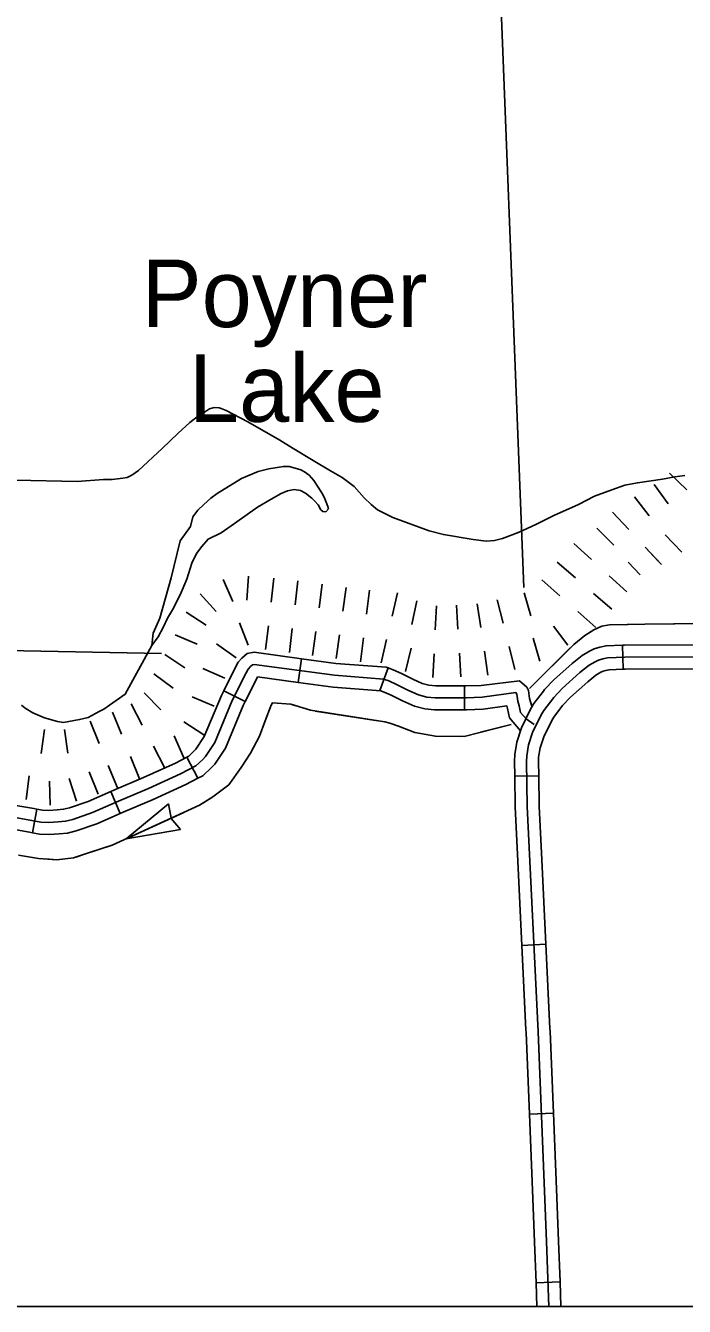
# Model space of a CAD drawing. Extents: x 1164457 to 1439835, y 1590918 to 1773502.
# Drawn here: x 1306270 to 1310389, y 1614471 to 1622480 of the extents above; entities that cross this region are included whole.
import ezdxf

# ---------------------------------------------------------------- set-up
doc = ezdxf.new("R2010")
doc.units = 0
for name, color, linetype in [('Level 29', 7, 'Continuous'), ('Level 31', 7, 'Continuous'), ('Level 32', 7, 'Continuous'), ('Level 35', 7, 'Continuous'), ('Level 43', 7, 'Continuous'), ('Level 5', 7, 'Continuous'), ('R_Draft', 7, 'Continuous')]:
    doc.layers.add(name, color=color, linetype=linetype)

msp = doc.modelspace()

# ---------------------------------------------------------------- linework, layer by layer
at = {"layer": 'Level 29'}
for p, q in [((1310296, 1619681.7), (1310403.6, 1619577.2)), ((1310199.4, 1619611), (1310288.4, 1619490.3)), ((1310077.7, 1619533.3), (1310168.8, 1619414.1)), ((1309939, 1619438.2), (1310041.3, 1619328.5)), ((1309939, 1619438.2), (1310041.3, 1619328.5)), ((1309842.3, 1619337), (1309948, 1619230.6)), ((1310270, 1619295.5), (1310373.5, 1619187)), ((1309698.2, 1619241.7), (1309808.9, 1619140.5)), ((1310143.6, 1619218.8), (1310245.9, 1619109.1)), ((1310143.6, 1619218.8), (1310226.2, 1619130.2)), ((1309593.5, 1619124.6), (1309707.4, 1619026.9)), ((1309593.5, 1619124.6), (1309707.4, 1619026.9)), ((1310038.6, 1619125.1), (1310112.2, 1619045)), ((1307664.6, 1619036.9), (1307653.1, 1618887.3)), ((1307664.6, 1619036.9), (1307653.1, 1618887.3)), ((1309919.6, 1619039.3), (1310030.3, 1618938.1)), ((1307505.4, 1619016.4), (1307565.4, 1618879)), ((1307823, 1619024.5), (1307805.6, 1618875.5)), ((1307972, 1619007.1), (1307954.6, 1618858.1)), ((1308125.1, 1618987.8), (1308104.8, 1618839.1)), ((1308125.1, 1618987.8), (1308104.8, 1618839.1)), ((1308274, 1618967.2), (1308253.5, 1618818.7)), ((1309496.9, 1619013.5), (1309609.6, 1618914.4)), ((1307362.1, 1618927.5), (1307461.7, 1618815.3)), ((1308419.7, 1618949), (1308401.3, 1618800.1)), ((1308595.3, 1618933.3), (1308561.3, 1618787.2)), ((1308595.3, 1618933.3), (1308561.3, 1618787.2)), ((1308716.5, 1618882), (1308685.4, 1618735.3)), ((1309219, 1618888.8), (1309255.9, 1618743.4)), ((1309388.3, 1618933.8), (1309430, 1618789.7)), ((1309821.2, 1618929.2), (1309935, 1618831.5)), ((1309821.2, 1618929.2), (1309935, 1618831.5)), ((1307273, 1618811.5), (1307399.8, 1618731.3)), ((1308838.9, 1618851.8), (1308831.7, 1618702)), ((1308965, 1618855.8), (1308973.6, 1618706.1)), ((1308965, 1618855.8), (1308973.6, 1618706.1)), ((1309093.8, 1618863.7), (1309116.2, 1618715.4)), ((1309722.2, 1618815.3), (1309834.8, 1618716.3)), ((1307606.9, 1618745.2), (1307662.4, 1618605.8)), ((1307788.2, 1618726.5), (1307770.8, 1618577.5)), ((1309569.8, 1618725.1), (1309659.8, 1618605.1)), ((1307205.2, 1618671), (1307342.9, 1618611.5)), ((1307937.2, 1618709.1), (1307919.7, 1618560.1)), ((1308084.6, 1618690.5), (1308064.3, 1618541.9)), ((1308084.6, 1618690.5), (1308064.3, 1618541.9)), ((1308233, 1618670.1), (1308212.5, 1618521.5)), ((1308382.9, 1618651.2), (1308364.6, 1618502.4)), ((1308527.3, 1618641.1), (1308493.3, 1618495)), ((1308527.3, 1618641.1), (1308493.3, 1618495)), ((1309444.7, 1618650), (1309486.4, 1618505.9)), ((1307463.1, 1618613.4), (1307585.9, 1618527.3)), ((1308680.4, 1618586.8), (1308644.5, 1618441.2)), ((1308982.1, 1618556.3), (1308990.7, 1618406.6)), ((1308982.1, 1618556.3), (1308990.7, 1618406.6)), ((1309138.6, 1618567.1), (1309161, 1618418.8)), ((1309292.8, 1618598), (1309329.6, 1618452.6)), ((1307141, 1618547.4), (1307266.2, 1618464.8)), ((1308824.4, 1618552.2), (1308817.2, 1618402.4)), ((1307072.6, 1618427.3), (1307191.6, 1618335.9)), ((1307377.4, 1618459.5), (1307514.6, 1618398.8)), ((1306930.3, 1618238.9), (1306999.7, 1618106)), ((1307010.7, 1618308.5), (1307115.6, 1618201.4)), ((1307311.6, 1618282.4), (1307449.6, 1618223.7)), ((1306812.3, 1618187), (1306869, 1618048.1)), ((1306388.1, 1618077.3), (1306367.5, 1617928.7)), ((1306513, 1618078.3), (1306533.7, 1617929.7)), ((1306673.5, 1618130.3), (1306730.1, 1617991.5)), ((1306673.5, 1618130.3), (1306730.1, 1617991.5)), ((1307259.3, 1618126.8), (1307384.5, 1618044.2)), ((1307198.5, 1618038.3), (1307259, 1617901)), ((1307198.5, 1618038.3), (1307259, 1617901)), ((1307069, 1617973), (1307138.4, 1617840)), ((1306786.8, 1617852.6), (1306843.5, 1617713.7)), ((1306786.8, 1617852.6), (1306843.5, 1617713.7)), ((1306925.7, 1617909.3), (1306982.4, 1617770.4)), ((1306293.1, 1617789.1), (1306272.4, 1617640.5)), ((1306418.3, 1617755.2), (1306423, 1617605.2)), ((1306542.7, 1617772.3), (1306588.8, 1617629.5)), ((1306667.4, 1617813.7), (1306722.8, 1617674.3))]:
    msp.add_line(p, q, dxfattribs=at)
for points in [[(1307658.5, 1620002.8), (1307524.6, 1620073.3), (1307492.2, 1620086.4), (1307479.8, 1620089.3), (1307448.6, 1620091), (1307420.5, 1620082.7), (1307388, 1620063.2), (1307362.4, 1620047.5), (1307296.9, 1619997.9), (1307224.8, 1619931.2), (1307124.2, 1619835.6), (1306976.8, 1619697.1), (1306933.5, 1619668.8), (1306904.7, 1619655.1), (1306878, 1619650.8), (1306811.5, 1619642), (1306757.2, 1619641.6), (1306591.9, 1619629.6), (1306206.2, 1619637.6)], [(1310393.1, 1619665.7), (1310330.1, 1619659.1), (1310253.2, 1619644.4), (1310095.6, 1619621.3), (1310017.4, 1619606.7), (1309935.4, 1619576.5), (1309826.3, 1619537.6), (1309726.8, 1619485.2), (1309572.1, 1619415.7), (1309460, 1619361.1), (1309356, 1619312), (1309252.3, 1619272.3), (1309201.9, 1619260.2), (1309149.5, 1619256.5), (1309069.4, 1619266.7), (1308882.1, 1619296.9), (1308792.7, 1619320.6), (1308565.5, 1619403.9), (1308469.3, 1619451.1), (1308431, 1619484.6), (1308386.5, 1619527.2), (1308324.3, 1619598.3), (1308250.2, 1619653.1), (1308176.7, 1619696.2), (1308067.2, 1619760.5), (1307937.6, 1619839.2), (1307859.1, 1619886.7), (1307658.5, 1620002.8)]]:
    msp.add_lwpolyline(points, dxfattribs=at)
at = {"layer": 'Level 31'}
for p, q in [((1310007.5, 1618455.5), (1310002.1, 1618605.4)), ((1310002.1, 1618605.4), (1310002.1, 1618605.4)), ((1309328.2, 1617785.4), (1309478.2, 1617788.2)), ((1309523, 1616735.4), (1309373.2, 1616728.2)), ((1309420.1, 1615673.8), (1309569.9, 1615679.9)), ((1309611.7, 1614624.3), (1309461.7, 1614619.1))]:
    msp.add_line(p, q, dxfattribs=at)
for points in [[(1310002.1, 1618605.4), (1309899.7, 1618601.8), (1309859.7, 1618593.3), (1309824.7, 1618582.4), (1309796.1, 1618568.2), (1309750.9, 1618541.5), (1309687.9, 1618491.9), (1309573.7, 1618388.4), (1309515.5, 1618328.2), (1309508.4, 1618318.9)], [(1310002.1, 1618605.4), (1310015.7, 1618605.9), (1310532.7, 1618607.1)], [(1310604.7, 1618532.2), (1310017.1, 1618530.9), (1309908.9, 1618527.1), (1309878.6, 1618520.6), (1309852.7, 1618512.6), (1309832, 1618502.2), (1309793.3, 1618479.5), (1309736.4, 1618434.6), (1309625.9, 1618334.4), (1309572.4, 1618279.2), (1309510.3, 1618198), (1309493.3, 1618170), (1309440.5, 1618060.5), (1309414.7, 1617981.8), (1309403.3, 1617913.1), (1309401.5, 1617878.6), (1309406.7, 1617597.2), (1309474.1, 1616187.6), (1309527.8, 1614875.7), (1309542, 1614470.8)], [(1310007.5, 1618455.5), (1309918.1, 1618452.3), (1309897.5, 1618448), (1309880.7, 1618442.8), (1309867.8, 1618436.3), (1309835.8, 1618417.4), (1309784.8, 1618377.3), (1309678.1, 1618280.5), (1309629.3, 1618230.1), (1309627.5, 1618227.7)], [(1310533, 1618457.1), (1310018.6, 1618455.9), (1310007.5, 1618455.5)], [(1309508.4, 1618318.9), (1309448.2, 1618240.3), (1309427.3, 1618205.8), (1309370.8, 1618088.5), (1309341.7, 1617999.8), (1309328.6, 1617921.2), (1309326.5, 1617879.8), (1309328.2, 1617785.4)], [(1309627.5, 1618227.7), (1309572.3, 1618155.7), (1309559.4, 1618134.3), (1309510.2, 1618032.4), (1309487.8, 1617963.9), (1309478, 1617905.1), (1309476.6, 1617877.4), (1309478.2, 1617788.2)], [(1309348, 1617255.6), (1309331.8, 1617594.7), (1309328.2, 1617785.4)], [(1309478.2, 1617788.2), (1309481.7, 1617599.7), (1309497.8, 1617262.8)], [(1309373.2, 1616728.2), (1309348, 1617255.6)], [(1309497.8, 1617262.8), (1309523, 1616735.4)], [(1309373.2, 1616728.2), (1309398.4, 1616200.8)], [(1309523, 1616735.4), (1309548.2, 1616208)], [(1309398.4, 1616200.8), (1309399.2, 1616184.2), (1309420.1, 1615673.8)], [(1309548.2, 1616208), (1309549, 1616190.9), (1309569.9, 1615679.9)], [(1309441.7, 1615146.2), (1309420.1, 1615673.8)], [(1309569.9, 1615679.9), (1309591.5, 1615152.4)], [(1309461.7, 1614619.1), (1309452.8, 1614872.9), (1309441.7, 1615146.2)], [(1309591.5, 1615152.4), (1309602.7, 1614878.6), (1309611.7, 1614624.3)], [(1309461.7, 1614619.1), (1309466.9, 1614470.8)], [(1309611.7, 1614624.3), (1309617, 1614470.8)]]:
    msp.add_lwpolyline(points, dxfattribs=at)
at = {"layer": 'Level 32'}
for p, q in [((1307974.9, 1618372.3), (1307995, 1618521)), ((1308483.9, 1618322.8), (1308536, 1618463.4)), ((1307642.6, 1618252.7), (1307508.5, 1618319.9)), ((1309014.5, 1618200.5), (1309014.5, 1618350.5)), ((1307347.8, 1617773.2), (1307277.7, 1617905.8)), ((1306862.1, 1617552.5), (1306802.2, 1617690)), ((1306313, 1617432.7), (1306340.6, 1617580.2))]:
    msp.add_line(p, q, dxfattribs=at)
for points in [[(1307508.5, 1618319.9), (1307582.5, 1618467.4), (1307599.6, 1618499), (1307622.4, 1618525), (1307654.5, 1618553.5), (1307698.1, 1618561.2), (1307995, 1618521)], [(1306205.3, 1617528), (1306308.3, 1617509.9), (1306365.7, 1617499.2), (1306415.4, 1617496.4), (1306472.8, 1617501.1), (1306520.1, 1617504.8), (1306565, 1617516.3), (1306688.7, 1617558.7), (1306850.3, 1617629.1), (1307038.2, 1617709.7), (1307239.3, 1617800.7), (1307333.5, 1617850.5), (1307377.5, 1617891.1), (1307394.2, 1617908.9), (1307453.9, 1617997.9), (1307562.4, 1618259.9), (1307649, 1618432.7), (1307661.5, 1618455.9), (1307675.8, 1618472), (1307688.5, 1618483.4), (1307699.6, 1618485.3), (1308201.9, 1618417.3), (1308507.7, 1618394), (1308540.2, 1618381.9), (1308588.5, 1618360), (1308659.4, 1618325.1), (1308725.7, 1618294.3), (1308778.9, 1618281.4), (1308830.7, 1618276.8), (1308885.5, 1618275.5), (1309024.6, 1618275.5), (1309125.1, 1618279.6), (1309335.9, 1618308.8), (1309337.7, 1618306), (1309341.3, 1618298.7), (1309348.6, 1618255.2), (1309356.7, 1618227.2), (1309364.9, 1618185.5), (1309399.8, 1618144.2), (1309450.1, 1618108.7)], [(1307995, 1618521), (1308209.8, 1618491.9), (1308523.9, 1618467.9), (1308536, 1618463.4)], [(1307642.6, 1618252.7), (1307715.5, 1618398), (1307720.3, 1618406.8), (1307974.9, 1618372.3)], [(1308536, 1618463.4), (1308568.8, 1618451.3), (1308620.5, 1618427.8), (1308691.7, 1618392.8), (1308750.6, 1618365.5), (1308791.1, 1618355.6), (1308834.9, 1618351.8), (1308886.5, 1618350.5), (1309014.5, 1618350.5)], [(1307277.7, 1617905.8), (1307289.8, 1617912.2), (1307324.6, 1617944.4), (1307335.3, 1617955.8), (1307387.4, 1618033.5), (1307494.1, 1618291.1), (1307508.5, 1618319.9)], [(1307974.9, 1618372.3), (1308194, 1618342.7), (1308491.5, 1618320), (1308483.9, 1618322.8)], [(1308483.9, 1618322.8), (1308511.6, 1618312.5), (1308556.4, 1618292.2), (1308627, 1618257.4), (1308700.8, 1618223.2), (1308766.7, 1618207.2), (1308826.4, 1618201.9), (1308884.6, 1618200.5), (1309014.5, 1618200.5)], [(1309014.5, 1618350.5), (1309023, 1618350.5), (1309118.4, 1618354.3), (1309357.8, 1618381.7), (1309403.2, 1618342.7), (1309413.5, 1618322.1), (1309421.8, 1618271.9), (1309435.8, 1618224.1)], [(1307347.8, 1617773.2), (1307377.2, 1617788.7), (1307430.4, 1617837.9), (1307453.1, 1617862.1), (1307520.3, 1617962.4), (1307630.6, 1618228.7), (1307642.6, 1618252.7)], [(1309014.5, 1618200.5), (1309026.1, 1618200.5), (1309131.8, 1618204.8), (1309279.2, 1618225.2), (1309283.8, 1618209.5), (1309295.1, 1618151.9), (1309364.6, 1618069.7)], [(1306802.2, 1617690), (1306820.5, 1617698), (1307007.9, 1617778.3), (1307206.3, 1617868.1), (1307277.7, 1617905.8)], [(1306862.1, 1617552.5), (1306880, 1617560.3), (1307068.4, 1617641), (1307272.3, 1617733.3), (1307347.8, 1617773.2)], [(1305836, 1617722.4), (1305892.2, 1617711.8), (1305937.5, 1617703), (1306001.5, 1617689.7), (1306036.9, 1617673.2), (1306076.6, 1617650), (1306123, 1617633.4), (1306157.2, 1617618), (1306221.2, 1617601.4), (1306321.7, 1617583.7), (1306340.6, 1617580.2)], [(1306340.6, 1617580.2), (1306374.7, 1617573.8), (1306414.5, 1617571.6), (1306466.8, 1617575.8), (1306507.7, 1617579.1), (1306543.5, 1617588.2), (1306661.5, 1617628.7), (1306802.2, 1617690)], [(1305808.3, 1617575), (1305864, 1617564.5), (1305907.9, 1617555.9), (1305953.8, 1617546.4), (1305967.1, 1617540.2), (1306013, 1617513.4), (1306066.8, 1617494.2), (1306107.2, 1617476), (1306189.4, 1617454.7), (1306294.9, 1617436.1), (1306313, 1617432.7)], [(1306313, 1617432.7), (1306356.7, 1617424.5), (1306416.4, 1617421.2), (1306478.8, 1617426.3), (1306532.4, 1617430.6), (1306586.5, 1617444.4), (1306715.9, 1617488.7), (1306862.1, 1617552.5)]]:
    msp.add_lwpolyline(points, dxfattribs=at)
at = {"layer": 'Level 35'}
for points in [[(1307058.5, 1618603), (1307067.4, 1618679.9), (1307109.8, 1618773.6), (1307180.4, 1619027.3), (1307235.8, 1619257.1), (1307300.8, 1619347.7), (1307315.2, 1619408), (1307346.4, 1619449.2), (1307383.9, 1619486.1), (1307427.7, 1619523.9), (1307467.1, 1619554.3), (1307619.1, 1619647.3), (1307724.8, 1619691.6), (1307791.5, 1619707.9), (1307882, 1619723.6), (1307918.4, 1619721.9), (1307955.4, 1619712.9), (1307990, 1619702.2), (1308013.1, 1619689.7), (1308043.8, 1619668.6), (1308073.2, 1619635.5), (1308100.1, 1619594.6), (1308127.9, 1619547.5), (1308140.1, 1619520.6), (1308149.4, 1619499.4), (1308159.7, 1619473), (1308163.5, 1619457.9), (1308148, 1619438.7)], [(1308148, 1619438.7), (1308127.7, 1619441.6), (1308115.1, 1619452.7), (1308098.5, 1619483.5), (1308075.8, 1619509.2), (1308059.6, 1619525.6), (1308020.6, 1619556.4), (1307989.2, 1619573.6), (1307949.7, 1619580), (1307908.3, 1619571.4), (1307867.4, 1619554.6), (1307805.6, 1619518.2), (1307719.7, 1619467.9), (1307575.4, 1619367.2), (1307491.7, 1619307.3), (1307410.7, 1619268.7), (1307371.5, 1619222.4), (1307339.5, 1619179.5), (1307308.5, 1619118.9), (1307278.3, 1619018.8), (1307237.1, 1618919.8), (1307187.4, 1618825.9), (1307157.9, 1618773.5), (1307130.6, 1618715.3), (1307098.2, 1618658.6), (1307058.5, 1618603)], [(1306243.5, 1618229.7), (1306267.3, 1618211.9), (1306315.2, 1618181.7), (1306388.8, 1618152.1), (1306469.9, 1618129.3), (1306506.5, 1618122.9), (1306607.2, 1618140.1), (1306662, 1618153.6), (1306730.4, 1618190), (1306759.7, 1618205.5), (1306892.9, 1618298.9), (1307058.5, 1618603)]]:
    msp.add_lwpolyline(points, dxfattribs=at)
at = {"layer": 'Level 43'}
for p, q in [((1306899.2, 1617395.3), (1307164, 1617613.7)), ((1307164, 1617613.7), (1307179.1, 1617523.5)), ((1307237.7, 1617452), (1307179.6, 1617522.5)), ((1306899.2, 1617395.3), (1307237.7, 1617452))]:
    msp.add_line(p, q, dxfattribs=at)
for points in [[(1311972.6, 1619042.7), (1311976, 1618965.1), (1311986.3, 1618765.3), (1311984.1, 1618761.5), (1310685.8, 1618743.4), (1310142.8, 1618737), (1309921.2, 1618731.8), (1309873.5, 1618724.1), (1309823.3, 1618702.2), (1309766.6, 1618666.1), (1309697, 1618609.4), (1309420.3, 1618335.4)], [(1310330.2, 1618739.2), (1310142.8, 1618737), (1309934.3, 1618732.1)], [(1309809.9, 1618693.7), (1309766.6, 1618666.1), (1309697, 1618609.4), (1309656.6, 1618569.4)], [(1309656.6, 1618569.4), (1309515.9, 1618430.1)], [(1309422.1, 1618337.2), (1309420.3, 1618335.4)], [(1309305.7, 1618109.9), (1309011.2, 1618035.3), (1308832.1, 1618036.5), (1308703.9, 1618058.5), (1308601.9, 1618098.8), (1308547.6, 1618118.4), (1308517, 1618125.8), (1308050.6, 1618198.5), (1307929.3, 1618236.4), (1307812.8, 1618244), (1307806.4, 1618230.8), (1307767.6, 1618131.4), (1307733.1, 1618037.2), (1307675.9, 1617930.5), (1307617.3, 1617839.9), (1307541.2, 1617732.3), (1307440.6, 1617656.8), (1307357.7, 1617604.3), (1306811.7, 1617355.4), (1306631.5, 1617296), (1306568.4, 1617276.1), (1306466.1, 1617263.1), (1306350, 1617271.7), (1306225.3, 1617291.8)], [(1307953.1, 1618228.9), (1307929.3, 1618236.4), (1307812.8, 1618244), (1307806.4, 1618230.8), (1307767.6, 1618131.4), (1307733.1, 1618037.2), (1307717.8, 1618008.5)], [(1308471.4, 1618132.9), (1308080.2, 1618193.9)], [(1308985, 1618035.5), (1308832.1, 1618036.5), (1308703.9, 1618058.5), (1308601.9, 1618098.8), (1308598.8, 1618100)], [(1309305.7, 1618109.9), (1309113.8, 1618061.3)], [(1307652.3, 1617894), (1307617.3, 1617839.9), (1307541.2, 1617732.3), (1307440.6, 1617656.8), (1307378.1, 1617617.2)], [(1307259.5, 1617559.6), (1306899.2, 1617395.3)], [(1306589.5, 1617282.7), (1306568.4, 1617276.1), (1306466.1, 1617263.1), (1306393.5, 1617268.5)], [(1306777.7, 1617344.2), (1306631.5, 1617296), (1306589.5, 1617282.7)]]:
    msp.add_lwpolyline(points, dxfattribs=at)
at = {"layer": 'Level 5'}
for points in [[(1309196.2, 1623807.8), (1309384.8, 1618966.5)], [(1305069.8, 1618592.2), (1307119.1, 1618553.8)]]:
    msp.add_lwpolyline(points, dxfattribs=at)
at = {"layer": 'R_Draft'}
msp.add_lwpolyline([(1246398.1, 1678582), (1349820.2, 1678582), (1349820.2, 1614470.8), (1246398.1, 1614470.8)], close=True, dxfattribs=at)

# ---------------------------------------------------------------- texts
at = {"layer": 'Level 35'}
for s, p in [('Poyner', (1306994.2, 1620594.8)), ('Lake', (1307290.8, 1620002.1))]:
    msp.add_text(s, height=422, dxfattribs=at).set_placement(p)

doc.saveas('drawing.dxf')
